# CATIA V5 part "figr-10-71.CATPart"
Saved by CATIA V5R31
Part number: Part1
Bounding box of the stored display mesh (mm): x -45.985 to 45.985, y -45.985 to 45.985, z -55 to 3.515
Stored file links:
  D:\PROJECTS\Project 2021\US EDITION\CATIA V5 6R 2021\Resources\Part Files\c10_catia_v5_6r2021_prt\c10_catia_v5_6r2021_prt\figr-10-71.CATPart
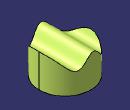
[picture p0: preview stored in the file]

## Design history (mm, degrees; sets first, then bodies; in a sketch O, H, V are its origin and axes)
Set1
  Sketch1 on xy-plane, origin (0, 0, 0), H (-1, 0, 0), V (0, -1, 0)
    circle A1 centre (0, 0) radius 45.985
  Extrude1: Element1 Sketch1, Lim1 56, Lim2 55, Direction xy-plane
  Sketch2 on zx-plane, origin (0, 0, 0), H (1, 0, 0), V (0, 0, -1)
    spline S1 through (-80.5635, 24.8913) (-73.6025, 19.8803) (-54.8525, -3.3629) (-35.1982, 19.8803) (-2.6271, -1.6506) (16.6996, 17.2854) (52.4104, -6.7877) (63.5409, 1.5862)
  Extrude2: Element1 Sketch2, Lim1 72, Lim2 69, Direction Sketch1.V
  Split1: ToCut Extrude1, Cutting Extrude2
  Trim1: Element1 Extrude1, Element2 Extrude2
  Trim2: Element1 Extrude1, Element2 Extrude2
Body1 (main body)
